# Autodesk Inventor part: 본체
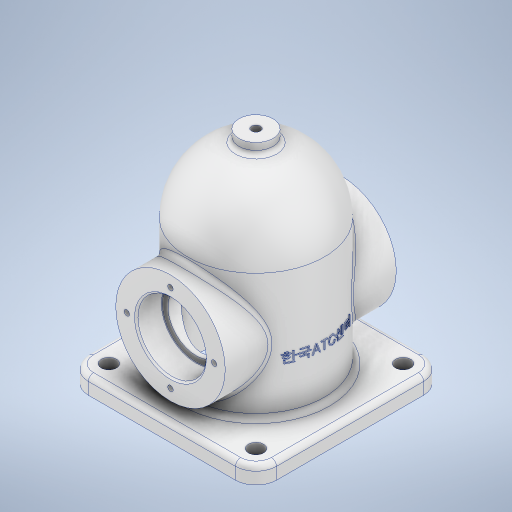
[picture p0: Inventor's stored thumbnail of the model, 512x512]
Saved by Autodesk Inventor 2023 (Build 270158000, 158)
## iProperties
Created: 2025-04
Part Number: 본체
Material: 알루미늄 6061
Document SubType Name: Modeling
Designer: ADMIN_PC
Density: 2.7 g/cm^3
Appearance: 알루미늄 - 평지
Author: ADMIN_PC
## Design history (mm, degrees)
sketch "스케치1"
  geometry: L1 (-57.941, 0)-(9.657, 0) reference; L2 (0, -26.457)-(0, 158.741) reference; L3 (-40, 0)-(-40, 84); L4 (0, 84)-(0, 0); L5 (-40, 0)-(0, 0); L6 (0, 124)-(0, 84); A1 r 40 centre (0, 84) between (0, 124) and (-40, 84); 1 further point
  constraints: 8 end point, 3 collinear, 3 point on line, 2 point on circle, 1 centre point, 1 coincident, 1 vertical
  dimensions: "d0" = 40 radius of A1; "d1" = 84 distance of L3.start L3.end; "d2" = 40 distance of L3.start L4.end
revolve "회전1" sketch "스케치1" stored, may be unused: angle "d3" = 90 deg
sketch "스케치2"
  geometry: C1 r 10 at (0, 0); 1 further point
  constraints: 1 centre point, 1 coincident
  dimensions: "d4" = 20 diameter of C1
extrude "돌출1" join sketch "스케치2" distance "d5" = 129; taper "d6" = 0 deg
sketch "스케치5"
  geometry: L1 (70.565, 48)-(-94.644, 48); L2 (-40, 0)-(40, 0) reference; L3 (0, -25.8)-(0, 154.8) reference; C1 r 32 at (0, 48); 1 further point
  constraints: 2 end point, 2 point on line, 1 centre point, 1 horizontal
  dimensions: "d11" = 48 distance between parallel lines of L2 L1; "d12" = 64 diameter of C1
extrude "돌출2" join sketch "스케치5" stored distance "d13" = 100; taper "d14" = 0 deg
sketch "스케치6"
  geometry: L1 (84, 60.933)-(84, -69.308); L2 (84, 40)-(84, -40) reference; L3 (0, 40)-(0, -40) reference; L4 (84, 32)-(84, 0); L5 (84, 0)-(116, 0); L6 (-25.8, 0)-(154.8, 0) reference; A1 r 32 centre (84, 0) between (116, 0) and (84, 32); 1 further point
  constraints: 6 end point, 2 collinear, 2 point on circle, 2 point on line, 1 centre point, 1 midpoint
  dimensions: "d15" = 84 distance between parallel lines of L3 L1; "d16" = 64 diameter of A1
revolve "회전3" sketch "스케치6" stored, may be unused: angle "d17" = 90 deg
sketch "스케치8"
  geometry: L1 (-58.34, 0)-(75.198, 0); L2 (-40, -48)-(40, -48) reference; L3 (0, -73.8)-(0, 106.8) reference; C1 r 20 at (0, 0); 1 further point
  constraints: 2 end point, 2 point on line, 1 centre point, 1 horizontal
  dimensions: "d21" = 48 distance between parallel lines of L2 L1; "d22" = 40 diameter of C1
extrude "돌출4" cut sketch "스케치8" distance "d23" = 15; taper "d24" = 0 deg
sketch "스케치9"
  geometry: L1 (0, -73.8)-(0, 106.8) reference; L2 (-61.351, 0)-(68.471, 0); L3 (-40, -48)-(40, -48) reference; C1 r 16.5 at (0, 0); 1 further point
  constraints: 2 end point, 2 point on line, 1 centre point, 1 horizontal
  dimensions: "d25" = 33 diameter of C1; "d26" = 48 distance between parallel lines of L3 L2
extrude "돌출5" cut sketch "스케치9" extent not by distance; stored distance "d27" = 0; taper "d28" = 0 deg
sketch "스케치11"
  geometry: L1 (-56, 0)-(56, 0) reference; L2 (0, 70)-(0, -70) reference; 2 further points
  constraints: 1 coincident
hole "구멍1" sketch "스케치11" at (0, 0) diameter "d29" = 5.1881; stored, may be unused: countersink angle "d33" = 90 deg, drill point angle "d35" = 118 deg; dims "d30" = 20, "d31" = 4, "d32" = 2, "d34" = 16
sketch "스케치14"
  geometry: L1 (-61.351, 0)-(72.449, 0); L2 (-40, -48)-(40, -48) reference; L3 (0, -73.8)-(0, 106.8) reference; 2 further points
  constraints: 2 end point, 1 horizontal, 1 point on line
  dimensions: "d36" = 48 distance between parallel lines of L2 L1; "d37" = 51 diameter of point (0, 25.5) L1
hole "구멍2" sketch "스케치14" at (0, 25.5) diameter "d38" = 3.242; stored, may be unused: countersink angle "d42" = 90 deg, drill point angle "d44" = 118 deg; dims "d39" = 8, "d40" = 4, "d41" = 2, "d43" = 10
sketch "스케치15"
  geometry: L1 (55, 55)-(-55, 55); L2 (-55, 55)-(-55, -55); L3 (-55, -55)-(55, -55); L4 (55, -55)-(55, 55); L5 (55, 55)-(-55, -55); L6 (-55, 55)-(55, -55); C1 r 2.594 at (0, 0) reference; 1 further point
  constraints: 12 end point, 2 midpoint, 2 parallel, 1 horizontal, 1 perpendicular
  dimensions: "d48" = 110 distance of L3.end L2.end; "d49" = 110 distance of L2.end L1.end
extrude "돌출6" join sketch "스케치15" distance "d50" = 10; taper "d51" = 0 deg
fillet "모깎기1" dims "d52" = 12
sketch "스케치16"
  geometry: C1 r 4.5 at (-43, 43); C2 r 4.5 at (-43, -43); C3 r 4.5 at (43, 43); C4 r 4.5 at (43, -43); A1 r 12 centre (-43, 43) between (-43, 55) and (-55, 43) reference; A2 r 12 centre (-43, -43) between (-55, -43) and (-43, -55) reference; A3 r 12 centre (43, 43) between (55, 43) and (43, 55) reference; A4 r 12 centre (43, -43) between (43, -55) and (55, -43) reference; 1 further point
  constraints: 4 centre point, 4 coincident
  dimensions: "d53" = 9 diameter of C1; "d54" = 9 diameter of C2; "d55" = 9 diameter of C3; "d56" = 9 diameter of C4
extrude "돌출7" cut sketch "스케치16" extent not by distance; stored distance "d57" = 0; taper "d58" = 0 deg
node "작업 평면1"
sketch "스케치17"
  geometry: L1 (-37.8, 0)-(156.8, 0) reference; 6 further points; 1 other entity
  constraints: 1 point on line, 2 other
  dimensions: "d60" = 30 dimension on point (40, 0)
feature "엠보싱1" sketch "스케치17" dims "d61" = 0.5, "d62" = 0
chamfer "모따기1" distance "d64" = 1; stored, may be unused: second distance "d65" = 2, angle "d66" = 45 deg
sketch "스케치20"
  geometry: C1 r 2.594 at (43, 55) reference; C2 r 32 at (43, 55); 1 further point
  constraints: 1 centre point, 1 coincident
  dimensions: "d70" = 64 diameter of C2
extrude "돌출9" cut sketch "스케치20" distance "d71" = 84; taper "d72" = 0 deg
fillet "모깎기3" dims "d73" = 3
fillet "모깎기4" dims "d74" = 0.3
feature "Ͳ耀ʹ耀Ͷ耀͸耀ͺ耀ͼ耀;耀΀耀" dims "d0" = 40, "d1" = 84, "d2" = 40, "d3" = 90 deg, "d4" = 20, "d5" = 129, "d6" = 0, "d11" = 48, "d12" = 64, "d13" = 100, "d14" = 0, "d15" = 84, "d16" = 64, "d17" = 90 deg, "d21" = 48, "d22" = 40, "d23" = 15, "d24" = 0, "d25" = 33, "d26" = 48, "d27" = 0, "d28" = 0, "d29" = 5.1881, "d30" = 20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
node "솔리드1"
mirror "미러1"
pattern_circular "원형 패턴1" dims angle "d46" = 360 deg
mirror "미러2"
feature "A9D066F2-1C7D-4E18-AEED-F7BC21143FA4" dims "d29" = 5.1881, "d30" = 20, "d31" = 4, "d32" = 2, "d33" = 90 deg, "d34" = 16, "d35" = 118 deg
